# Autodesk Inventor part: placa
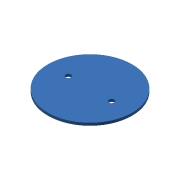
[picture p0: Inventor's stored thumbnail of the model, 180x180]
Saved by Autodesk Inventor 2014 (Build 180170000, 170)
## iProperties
Created: 2012-09
Part Number: placa
Material: Generic
Document SubType Name: Modeling
Designer: TR-06
Density: 1 g/cm^3
Appearance: Default
Author: TR-06
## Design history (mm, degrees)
sketch "Sketch1"
  geometry: C1 r 97 at (0, 0); C2 r 6.25 at (50, 0); C3 r 6.25 at (-50, 0); 1 further point
  constraints: 3 centre point, 1 coincident
  dimensions: "d0" = 194 diameter of C1; "d1" = 12.5 diameter of C2; "d2" = 12.5 diameter of C3; "d3" = 100 distance of C2.centre C3.centre
extrude "Extrusion1" new body sketch "Sketch1" stored distance "d6" = 6; taper "d7" = 0 deg
body "Solid1"
